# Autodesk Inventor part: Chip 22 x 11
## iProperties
Company: Autodesk Inc.
Created: 2005-12
Part Number: Chip 22 x 11
Document SubType Name: Modeling
Designer: Autodesk Inc.
Density: 1 g/cm^3
Author: Autodesk Inc.
Title: Personal Computer
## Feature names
1. Extrusion1
2. Extrusion3
3. Rectangular Pattern2
4. Mirror3
5. Extrusion4
6. Rectangular Pattern3
7. Mirror4
8. Chamfer1
